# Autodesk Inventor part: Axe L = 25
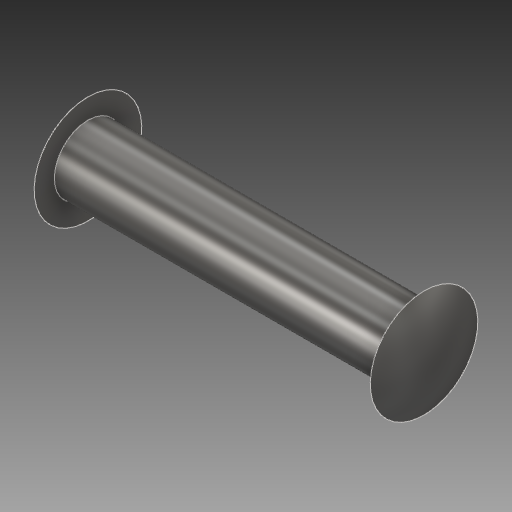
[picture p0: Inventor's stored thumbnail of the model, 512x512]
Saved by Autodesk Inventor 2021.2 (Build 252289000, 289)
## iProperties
Created: 2018-06
Part Number: Axe L = 25
Material: Acier inoxydable
Document SubType Name: Modeling
Designer: Fabian Perrée
Density: 8 g/cm^3
Appearance: Semi-poli
Author: Fabian Perrée
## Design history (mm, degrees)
sketch "Esquisse1"
  geometry: L1 (-12.5, 0)-(12.5, 0); L2 (12.5, 2.5)-(-12.5, 2.5); L3 (12.5, 2.5)-(12.5, 4); L4 (12.5, 0)-(13.572, 0); L5 (0, 2.5)-(0, 0); L6 (-12.5, 2.5)-(-12.5, 4); L7 (-13.572, 0)-(-12.5, 0); A1 r 8 centre (5.572, 0) between (13.572, 0) and (12.5, 4); A2 r 8 centre (-5.572, 0) between (-12.5, 4) and (-13.572, 0); 1 further point
  constraints: 14 end point, 4 horizontal, 4 point on circle, 3 symmetric about line, 2 centre point, 2 midpoint, 2 point on line, 1 coincident, 1 perpendicular, 1 vertical, 1 other
  dimensions: "d0" = 25 distance of L1.start L1.end; "d1" = 5 diameter of L2 L1; "d2" = 8 diameter of L3.end L1; "d3" = 16 diameter of A1
revolve "Révolution1" sketch "Esquisse1" stored, may be unused: angle "d4" = 90 deg
node "Solide1"
